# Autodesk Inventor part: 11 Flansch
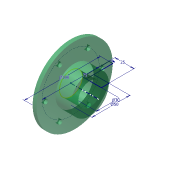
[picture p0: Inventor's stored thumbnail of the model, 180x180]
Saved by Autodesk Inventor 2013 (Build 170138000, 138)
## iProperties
Created: 2012-10
Part Number: 11 Flansch
Material: Allgemein
Vendor: www.inventor-faq.de
Document SubType Name: Modeling
Designer: Administrator
Manufacturer: www.inventor-faq.de
Density: 1 g/cm^3
RuleStatus: InUse
AfterDocOpen0: inventorfaq
BeforeDocSave0: inventorfaq
Author: Administrator
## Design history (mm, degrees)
sketch "Skizze1"
  geometry: L1 (0, 15)-(5, 15); L2 (5, 15)-(5, 50); L3 (5, 50)-(0, 50); L4 (0, 50)-(0, 15); L5 (5, 15)-(25, 15); L6 (25, 15)-(25, 25); L7 (25, 25)-(5, 25); L8 (5, 25)-(5, 15); L9 (0, 0)-(36.757, 0)
  constraints: 18 end point, 4 parallel, 3 perpendicular, 2 horizontal, 1 vertical alignment
  dimensions: "d0" = 5 distance of L2.end L3.end; "d2" = 30 diameter of L5 L9; "d3" = 50 diameter of L7 L9; "d4" = 100 diameter of L3 L9; "d5" = 25 distance between parallel lines of L6 L4
revolve "Umdrehung1" sketch "Skizze1" stored, may be unused: angle "d6" = 90 deg
sketch "Skizze2" dims "d7" = 75
  geometry: C1 r 15 at (0, 0) reference; 2 further points
  constraints: 2 vertical alignment, 1 coincident, 2 other
hole "Bohrung1" sketch "Skizze2" at (0, 37.5) diameter "d8" = 5.5; stored, may be unused: countersink angle "d12" = 90 deg, drill point angle "d14" = 118 deg; dims "d9" = 6, "d10" = 4, "d11" = 2, "d13" = 8
pattern_circular "Runde Anordnung1" dims angle "d16" = 360 deg
node "Volumenkörper1"
